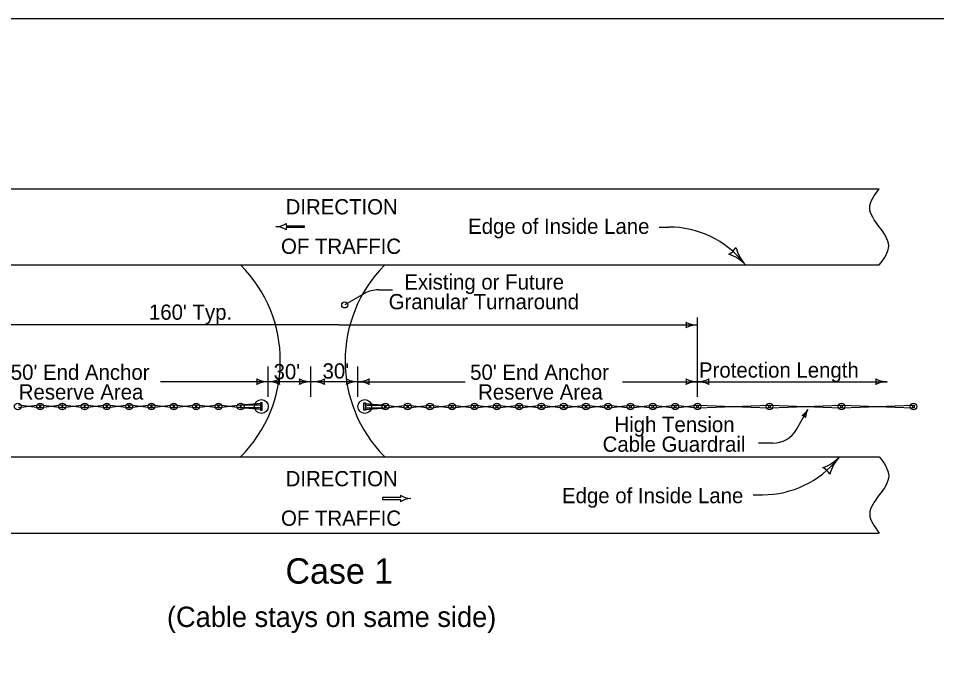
# Model space of a CAD drawing. Extents: x 10133 to 81668, y 7924 to 11018.
# Drawn here: x 10688 to 11411, y 9431 to 9944 of the extents above; entities that cross this region are included whole.
import ezdxf

# ---------------------------------------------------------------- set-up
doc = ezdxf.new("R2010")
doc.units = 0
for name, color, linetype in [('dsnCellElements', 7, 'Continuous'), ('DsnShtRevisedText', 7, 'Continuous'), ('dsnStdDimension', 7, 'Continuous'), ('Level 8', 7, 'Continuous'), ('SheetBorder', 7, 'Continuous')]:
    doc.layers.add(name, color=color, linetype=linetype)

msp = doc.modelspace()

# ---------------------------------------------------------------- linework, layer by layer
at = {"layer": 'dsnCellElements'}
for p, q in [((10704.94, 9639.73), (10688.31, 9637.47)), ((10704.94, 9637.47), (10688.31, 9639.72)), ((10722.46, 9637.47), (10705.88, 9639.73)), ((10722.46, 9639.72), (10705.88, 9637.47)), ((10740.03, 9639.72), (10723.4, 9637.47)), ((10740.03, 9637.47), (10723.4, 9639.72)), ((10757.56, 9637.47), (10740.97, 9639.72)), ((10757.56, 9639.72), (10740.97, 9637.47)), ((10775.12, 9639.72), (10758.49, 9637.47)), ((10775.12, 9637.47), (10758.49, 9639.72)), ((10792.65, 9639.72), (10776.06, 9637.47)), ((10792.65, 9637.47), (10776.06, 9639.72)), ((10810.23, 9639.72), (10793.6, 9637.47)), ((10810.23, 9637.47), (10793.6, 9639.72)), ((10827.75, 9639.72), (10811.16, 9637.47)), ((10827.75, 9637.47), (10811.16, 9639.72)), ((10845.33, 9639.72), (10828.7, 9637.47)), ((10845.33, 9637.47), (10828.7, 9639.72)), ((10862.85, 9639.72), (10846.27, 9637.47)), ((10862.85, 9637.47), (10846.27, 9639.72)), ((10879.61, 9640.91), (10862.85, 9639.72)), ((10879.61, 9636.29), (10862.85, 9637.47)), ((10879.61, 9639.72), (10863.78, 9639.72)), ((10879.61, 9637.47), (10863.78, 9637.47)), ((10960.95, 9640.91), (10977.71, 9639.72)), ((10960.95, 9639.72), (10976.77, 9639.72)), ((10960.95, 9637.47), (10976.77, 9637.47)), ((10960.95, 9636.29), (10977.71, 9637.47)), ((10977.71, 9639.72), (10994.29, 9637.47)), ((10977.71, 9637.47), (10994.29, 9639.72)), ((10995.23, 9639.72), (11011.86, 9637.47)), ((10995.23, 9637.47), (11011.86, 9639.72)), ((11012.81, 9639.72), (11029.39, 9637.47)), ((11012.81, 9637.47), (11029.39, 9639.72)), ((11030.33, 9639.72), (11046.96, 9637.47)), ((11030.33, 9637.47), (11046.96, 9639.72)), ((11047.91, 9639.72), (11064.49, 9637.47)), ((11047.91, 9637.47), (11064.49, 9639.72)), ((11065.43, 9639.72), (11082.06, 9637.47)), ((11065.43, 9637.47), (11082.06, 9639.72)), ((11083, 9637.47), (11099.58, 9639.72)), ((11083, 9639.72), (11099.58, 9637.47)), ((11100.52, 9639.72), (11117.15, 9637.47)), ((11100.52, 9637.47), (11117.15, 9639.72)), ((11118.09, 9637.47), (11134.67, 9639.73)), ((11118.09, 9639.72), (11134.67, 9637.47)), ((11135.61, 9639.73), (11152.24, 9637.47)), ((11135.61, 9637.47), (11152.24, 9639.72)), ((11153.18, 9637.47), (11169.76, 9639.73)), ((11153.18, 9639.72), (11169.76, 9637.48)), ((11170.7, 9639.73), (11187.33, 9637.47)), ((11170.7, 9637.48), (11187.33, 9639.72)), ((11188.27, 9637.47), (11204.85, 9639.73)), ((11188.27, 9639.72), (11204.85, 9637.48)), ((11205.79, 9639.73), (11222.42, 9637.47)), ((11205.79, 9637.48), (11222.42, 9639.72)), ((11223.36, 9639.72), (11279.12, 9637.47)), ((11223.36, 9637.47), (11279.12, 9639.72)), ((11280.06, 9639.72), (11335.82, 9637.47)), ((11280.06, 9637.47), (11335.82, 9639.72)), ((11336.76, 9639.72), (11392.53, 9637.47)), ((11336.76, 9637.47), (11392.53, 9639.72))]:
    msp.add_line(p, q, dxfattribs=at)
for points in [[(10705.88, 9637.47), (10705.88, 9639.73), (10704.94, 9639.73), (10704.94, 9637.47)], [(10723.4, 9637.47), (10723.4, 9639.72), (10722.46, 9639.72), (10722.46, 9637.47)], [(10740.97, 9637.47), (10740.97, 9639.72), (10740.03, 9639.72), (10740.03, 9637.47)], [(10758.49, 9637.47), (10758.49, 9639.72), (10757.56, 9639.72), (10757.56, 9637.47)], [(10776.06, 9637.47), (10776.06, 9639.72), (10775.12, 9639.72), (10775.12, 9637.47)], [(10793.58, 9637.47), (10793.58, 9639.72), (10792.65, 9639.72), (10792.65, 9637.47)], [(10811.16, 9637.47), (10811.16, 9639.72), (10810.23, 9639.72), (10810.23, 9637.47)], [(10828.69, 9637.47), (10828.69, 9639.72), (10827.75, 9639.72), (10827.75, 9637.47)], [(10846.27, 9637.47), (10846.27, 9639.72), (10845.33, 9639.72), (10845.33, 9637.47)], [(10863.79, 9637.47), (10863.79, 9639.72), (10862.85, 9639.72), (10862.85, 9637.47)], [(10880.22, 9635.6), (10880.22, 9641.6), (10879, 9641.6), (10879, 9635.6)], [(10960.34, 9635.6), (10960.34, 9641.6), (10961.56, 9641.6), (10961.56, 9635.6)], [(10976.77, 9637.47), (10976.77, 9639.72), (10977.71, 9639.72), (10977.71, 9637.47)], [(10994.29, 9637.47), (10994.29, 9639.72), (10995.23, 9639.72), (10995.23, 9637.47)], [(11011.87, 9637.47), (11011.87, 9639.72), (11012.81, 9639.72), (11012.81, 9637.47)], [(11029.39, 9637.47), (11029.39, 9639.72), (11030.33, 9639.72), (11030.33, 9637.47)], [(11046.97, 9637.47), (11046.97, 9639.72), (11047.91, 9639.72), (11047.91, 9637.47)], [(11064.49, 9637.47), (11064.49, 9639.72), (11065.43, 9639.72), (11065.43, 9637.47)], [(11082.06, 9637.47), (11082.06, 9639.72), (11083, 9639.72), (11083, 9637.47)], [(11099.58, 9637.47), (11099.58, 9639.72), (11100.52, 9639.72), (11100.52, 9637.47)], [(11117.15, 9637.47), (11117.15, 9639.72), (11118.09, 9639.72), (11118.09, 9637.47)], [(11134.67, 9637.47), (11134.67, 9639.73), (11135.61, 9639.73), (11135.61, 9637.47)], [(11152.24, 9637.47), (11152.24, 9639.72), (11153.18, 9639.72), (11153.18, 9637.47)], [(11169.76, 9637.48), (11169.76, 9639.73), (11170.7, 9639.73), (11170.7, 9637.48)], [(11187.33, 9637.47), (11187.33, 9639.72), (11188.27, 9639.72), (11188.27, 9637.47)], [(11204.85, 9637.48), (11204.85, 9639.73), (11205.79, 9639.73), (11205.79, 9637.48)], [(11222.42, 9637.47), (11222.42, 9639.72), (11223.36, 9639.72), (11223.36, 9637.47)], [(11222.42, 9637.47), (11222.42, 9639.72), (11223.36, 9639.72), (11223.36, 9637.47)], [(11279.12, 9637.47), (11279.12, 9639.72), (11280.06, 9639.72), (11280.06, 9637.47)], [(11279.12, 9637.47), (11279.12, 9639.72), (11280.06, 9639.72), (11280.06, 9637.47)], [(11335.82, 9637.47), (11335.82, 9639.72), (11336.76, 9639.72), (11336.76, 9637.47)], [(11335.82, 9637.47), (11335.82, 9639.72), (11336.76, 9639.72), (11336.76, 9637.47)], [(11392.53, 9637.47), (11392.53, 9639.72), (11393.46, 9639.72), (11393.46, 9637.47)]]:
    msp.add_lwpolyline(points, close=True, dxfattribs=at)
for centre, radius in [((10879.61, 9638.6), 5.4), ((10960.95, 9638.6), 5.4), ((10687.84, 9638.6), 2.66), ((10705.41, 9638.6), 2.66), ((10722.93, 9638.6), 2.66), ((10740.5, 9638.6), 2.66), ((10758.02, 9638.6), 2.66), ((10775.59, 9638.6), 2.66), ((10793.11, 9638.6), 2.66), ((10810.7, 9638.6), 2.66), ((10828.22, 9638.6), 2.66), ((10845.8, 9638.6), 2.66), ((10863.32, 9638.6), 2.66), ((10977.24, 9638.6), 2.66), ((10994.76, 9638.6), 2.66), ((11012.34, 9638.6), 2.66), ((11029.86, 9638.6), 2.66), ((11047.44, 9638.6), 2.66), ((11064.96, 9638.6), 2.66), ((11082.53, 9638.6), 2.66), ((11100.05, 9638.6), 2.66), ((11117.62, 9638.6), 2.66), ((11135.14, 9638.6), 2.66), ((11152.71, 9638.6), 2.66), ((11170.23, 9638.6), 2.66), ((11187.8, 9638.6), 2.66), ((11205.32, 9638.6), 2.66), ((11222.89, 9638.6), 2.66), ((11222.89, 9638.6), 2.66), ((11279.59, 9638.6), 2.66), ((11279.59, 9638.6), 2.66), ((11336.29, 9638.6), 2.66), ((11336.29, 9638.6), 2.66), ((11393, 9638.6), 2.66)]:
    msp.add_circle(centre, radius, dxfattribs=at)
at = {"layer": 'DsnShtRevisedText'}
for p, q in [((10899.21, 9782.68), (10899.21, 9780.9)), ((10899.21, 9780.9), (10913.18, 9780.9)), ((10913.18, 9780.9), (10913.18, 9779.38)), ((10891.11, 9780.14), (10891.11, 9780.14)), ((10913.18, 9779.38), (10899.21, 9779.38)), ((10899.21, 9779.38), (10899.21, 9777.6)), ((11192.88, 9779.82), (11200.32, 9779.82)), ((10971.71, 9730.4), (10982.96, 9730.4)), ((10960.85, 9727.57), (10945.3, 9718.52)), ((11222.89, 9646.12), (11222.89, 9708.74)), ((10940.6, 9702.74), (10617.66, 9702.74)), ((10940.6, 9702.74), (11222.89, 9702.74)), ((10885.01, 9646.12), (10885.01, 9670.12)), ((10918.61, 9646.12), (10918.61, 9670.12)), ((10955.55, 9646.12), (10955.55, 9670.12)), ((10885.01, 9658.12), (10800.33, 9658.12)), ((10955.55, 9658.12), (10885.01, 9658.12)), ((10955.55, 9658.12), (11040.03, 9658.12)), ((11163.78, 9658.12), (11222.89, 9658.12)), ((11222.89, 9658.12), (11245.36, 9658.12)), ((11245.36, 9658.12), (11372.3, 9658.12)), ((11300.95, 9620.59), (11309.83, 9636.24)), ((11282.14, 9609.79), (11270.89, 9609.79)), ((10989.05, 9566.95), (10975.09, 9566.95)), ((10975.09, 9566.95), (10975.09, 9565.43)), ((10975.09, 9565.43), (10989.05, 9565.43)), ((10989.05, 9568.73), (10989.05, 9566.95)), ((10989.05, 9565.43), (10989.05, 9563.65)), ((10997.15, 9566.19), (10997.15, 9566.19)), ((11266.79, 9569.16), (11274.24, 9569.16))]:
    msp.add_line(p, q, dxfattribs=at)
msp.add_circle((10945.3, 9718.52), 2.4, dxfattribs=at)
for centre, radius, start, end in [((10890.44, 9796.5), 16.37, 272.35199, 302.38203), ((10890.44, 9763.78), 16.37, 57.61797, 87.64801), ((11200.32, 9703.64), 76.18, 39.01063, 90), ((11242.33, 9769.82), 12.51, 295.26394, 330.73064), ((11284.52, 9772.04), 32.38, 194.9248, 222.99729), ((11237.16, 9727.88), 32.38, 42.99729, 71.06977), ((10787.79, 9674.49), 106.73, 315, 45), ((11052.25, 9674.49), 106.73, 135, 225), ((10971.58, 9708.63), 21.76, 89.65652, 119.54435), ((11206.86, 9702.74), 7.39, 342.26665, 17.73335), ((11222.89, 9721.87), 19.13, 241.92751, 270), ((11222.89, 9683.62), 19.13, 90, 118.07249), ((10868.97, 9658.12), 7.39, 342.26665, 17.73335), ((10885.01, 9677.25), 19.13, 241.92751, 270), ((10885.01, 9639), 19.13, 90, 118.07249), ((10885.01, 9677.25), 19.13, 270, 298.07249), ((10885.01, 9639), 19.13, 61.92751, 90), ((10901.04, 9658.12), 7.39, 162.26665, 197.73335), ((10902.57, 9658.12), 7.39, 342.26665, 17.73335), ((10918.61, 9677.25), 19.13, 241.92751, 270), ((10918.61, 9639), 19.13, 90, 118.07249), ((10920.28, 9677.25), 19.13, 270, 298.07249), ((10920.28, 9639), 19.13, 61.92751, 90), ((10936.31, 9658.12), 7.39, 162.26665, 197.73335), ((10939.51, 9658.12), 7.39, 342.26665, 17.73335), ((10955.55, 9677.25), 19.13, 241.92751, 270), ((10955.55, 9639), 19.13, 90, 118.07249), ((10955.55, 9677.25), 19.13, 270, 298.07249), ((10955.55, 9639), 19.13, 61.92751, 90), ((10971.58, 9658.12), 7.39, 162.26665, 197.73335), ((11206.86, 9658.12), 7.39, 342.26665, 17.73335), ((11222.89, 9677.25), 19.13, 241.92751, 270), ((11222.89, 9639), 19.13, 90, 118.07249), ((11222.89, 9677.25), 19.13, 270, 298.07249), ((11222.89, 9639), 19.13, 61.92751, 90), ((11238.93, 9658.12), 7.39, 162.26665, 197.73335), ((11356.26, 9658.12), 7.39, 342.26665, 17.73335), ((11372.3, 9677.25), 19.13, 241.92751, 270), ((11372.3, 9639), 19.13, 90, 118.07249), ((11298.07, 9643.09), 13.6, 301.69616, 329.76864), ((11321.58, 9629.4), 13.6, 149.76864, 177.84113), ((11304.08, 9626.39), 5.25, 42.03529, 77.50199), ((11282.14, 9631.55), 21.76, 270, 329.77566), ((11274.24, 9645.34), 76.18, 270, 320.98937), ((11311.08, 9621.1), 32.38, 288.93023, 317.00271), ((11358.44, 9576.94), 32.38, 137.00271, 165.0752), ((11316.24, 9579.16), 12.51, 29.26936, 64.73606), ((10997.82, 9582.55), 16.37, 237.61797, 267.64801), ((10997.82, 9549.83), 16.37, 92.35199, 122.38203)]:
    msp.add_arc(centre, radius, start, end, dxfattribs=at)
at = {"layer": 'dsnStdDimension'}
for p, q in [((10490.35, 9809.96), (11366.01, 9809.96)), ((10490.35, 9749.96), (11366.01, 9749.96)), ((10490.35, 9599.02), (11366.01, 9599.02)), ((10490.35, 9539.02), (11366.01, 9539.02))]:
    msp.add_line(p, q, dxfattribs=at)
for points in [[(11366.01, 9749.96), (11373.51, 9764.96), (11366.01, 9779.96), (11358.51, 9794.96), (11366.01, 9809.96)], [(11366.01, 9599.02), (11373.51, 9584.02), (11366.01, 9569.02), (11358.51, 9554.02), (11366.01, 9539.02)]]:
    msp.add_spline(points, degree=3, dxfattribs=at)
at = {"layer": 'SheetBorder'}
msp.add_lwpolyline([(10132.52, 9944.02), (13267.53, 9944.02), (13267.53, 7924.02), (10132.52, 7924.02)], close=True, dxfattribs=at)

# ---------------------------------------------------------------- texts
at = {"layer": 'DsnShtRevisedText'}
for s, p in [('DIRECTION', (10898.71, 9789.76)), ('Edge of Inside Lane', (11042.37, 9774.46)), ('OF TRAFFIC', (10895.1, 9758.7)), ('Existing or Future', (10992.16, 9730.63)), ('Granular Turnaround', (10979.84, 9715.1)), ("160' Typ.", (10791.11, 9706.86)), ("30'", (10927.78, 9660.58)), ('Protection Length', (11224.12, 9661.31)), ("50' End Anchor", (10682.35, 9659.58)), ("30'", (10889.23, 9660.04)), ("50' End Anchor", (11043.98, 9659.58)), ('Reserve Area', (10688.62, 9644.04)), ('Reserve Area', (11050.26, 9644.04)), ('High Tension', (11157.57, 9618.49)), ('Cable Guardrail', (11148.28, 9602.96)), ('DIRECTION', (10898.71, 9575.81)), ('Edge of Inside Lane', (11116.29, 9562.52)), ('OF TRAFFIC', (10895.1, 9544.75))]:
    msp.add_text(s, height=12, dxfattribs=at).set_placement(p)
at = {"layer": 'Level 8'}
for s, height, p in [('Case 1', 20, (10898.6, 9499.19)), ('(Cable stays on same side)', 16, (10805.3, 9465.12))]:
    msp.add_text(s, height=height, dxfattribs=at).set_placement(p)

doc.saveas('drawing.dxf')
